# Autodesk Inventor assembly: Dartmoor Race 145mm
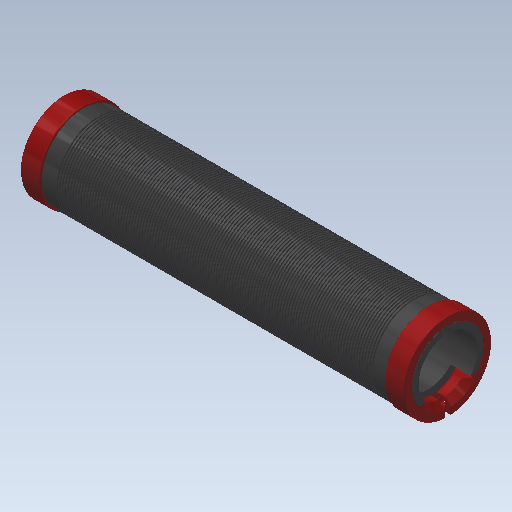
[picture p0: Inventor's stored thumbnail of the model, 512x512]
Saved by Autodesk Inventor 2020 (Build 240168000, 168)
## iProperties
Created: 2017-10
Part Number: Dartmoor Race 145mm
Material: Ogólny
Document SubType Name: Assembly
Designer: Tomasz
Sending System: SolidWorks 2017
Last Author: Tomasz
Last Saved: 2017-10-01
Author: Tomasz
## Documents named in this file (2)
- C:\Users\bruno\Documents\1-Cours-2020-21\1STI2D-2020-21\IT\6. Antivol\Inventor-Antivol\INVENTOR 2018_Steel Hardtail B+\Dartmoor Race 145mm.iam
- C:\Users\bruno\Documents\1-Cours-2020-21\1STI2D-2020-21\IT\6. Antivol\Inventor-Antivol\INVENTOR 2018_Steel Hardtail B+\Kopia Dartmoor Race 145mm.iam^Dartmoor Race 145mm.iam
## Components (1 placed, 1 different names)
1. Kopia Dartmoor Race 145mm.iam^Dartmoor Race 145mm:1 [sub-assembly]
